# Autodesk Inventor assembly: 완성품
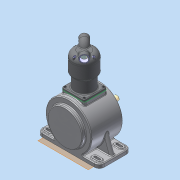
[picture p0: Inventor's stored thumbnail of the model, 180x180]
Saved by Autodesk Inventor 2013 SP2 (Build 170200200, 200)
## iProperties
Created: 2015-06
Part Number: 완성품
Document SubType Name: Assembly
Designer: dgall
Author: dgall
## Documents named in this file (15)
- C:\Documents and Settings\dgall\바탕 화면\450605V1017\완성품.iam
- C:\Documents and Settings\dgall\바탕 화면\450605V1017\본체.ipt
- C:\Documents and Settings\dgall\바탕 화면\450605V1017\베어링 6204.ipt
- C:\Documents and Settings\dgall\바탕 화면\450605V1017\메인 크랭크 축-구동부.ipt
- C:\Documents and Settings\dgall\바탕 화면\450605V1017\크랭크 서브축.ipt
- C:\Documents and Settings\dgall\바탕 화면\450605V1017\메인커버.ipt
- C:\Documents and Settings\dgall\바탕 화면\450605V1017\커넥팅 로드.ipt
- C:\Documents and Settings\dgall\바탕 화면\450605V1017\피스톤.ipt
- C:\Documents and Settings\dgall\바탕 화면\450605V1017\피스톤 핀.ipt
- C:\Documents and Settings\dgall\바탕 화면\450605V1017\베어링 NA 4902.ipt
- C:\Documents and Settings\dgall\바탕 화면\450605V1017\실린더.ipt
- C:\Documents and Settings\dgall\바탕 화면\450605V1017\실린더헤드.ipt
- C:\Documents and Settings\dgall\바탕 화면\450605V1017\오일실.ipt
- C:\Documents and Settings\dgall\바탕 화면\450605V1017\M4x0.7.ipt
- C:\Documents and Settings\dgall\바탕 화면\450605V1017\M5x0.8.ipt
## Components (14 placed, 4 different names)
1. 피스톤:1
2. 피스톤 핀:1
3. M4x0.7:1
4. M4x0.7:2
5. M4x0.7:3
6. M4x0.7:4
7. M4x0.7:5
8. M4x0.7:6
9. M4x0.7:7
10. M4x0.7:8
11. M5x0.8:1
12. M5x0.8:2
13. M5x0.8:3
14. M5x0.8:4
